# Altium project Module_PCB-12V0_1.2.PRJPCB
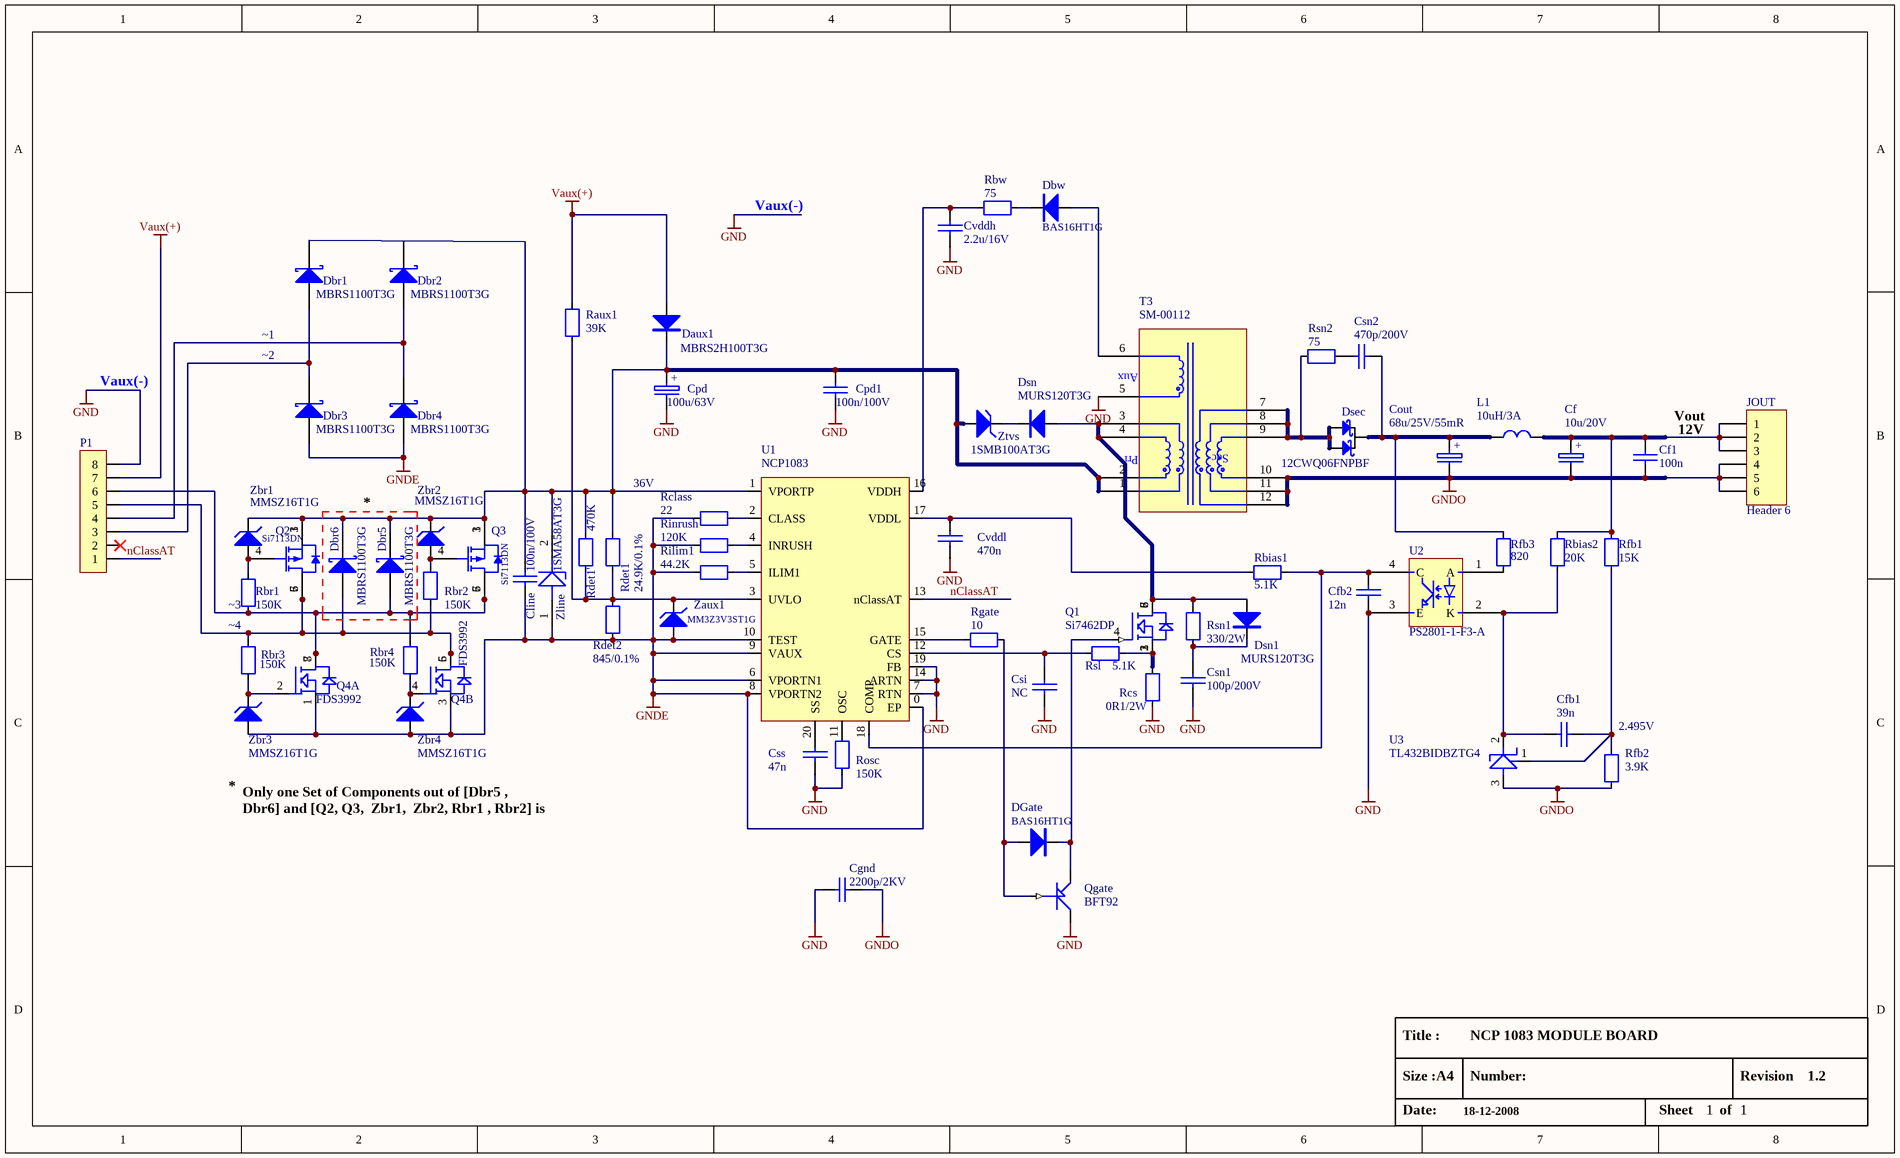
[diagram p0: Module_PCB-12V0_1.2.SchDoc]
1 sheet, 69 parts. Net scope: global (net labels, ports and power ports of the same name join across sheets).
Board file: Module_PCB-12V0_1.2.PcbDoc

## Sheet Module_PCB-12V0_1.2.SchDoc: NCP1081_COMPACT_MODULE
size Legal; Revision: 1; SheetNumber: 1; SheetTotal: 1; PageSetup: Record=PageOptions|CenterHorizontal=True|CenterVertical=True|PrintScale=0.80|XCorrection=1.00|YCorrection=1.00|PrintKind=2|BorderSize=5000000|LeftOffset=0|BottomOffset=0|Orientation=2|PaperLength=1000|PaperWidth=1000|Scale=100|PaperSource=7|PrintQuality=-4|MediaType=1|DitherType=10|PaperKind=A4|PrintScaleMode=1

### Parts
Cf  10u/20V  [C-TANT-B]
Cf1  100n  [0805-C-S]
Cfb1  39n  [0805-C-S]
Cfb2  12n  [0805-C-S]
Cgnd  2200p/2KV  [1812]
Cline  100n/100V  [1206-C]
Cout  68u/25V/55mR  [C-TANT-E]
Cpd  100u/63V  [CRD10.0L17.0RM5.0]
Cpd1  100n/100V  [1206-C]
Csi  NC  [0805-C-S]
Csn1  100p/200V  [0805-C-S]
Csn2  470p/200V  [0805-C-S]
Css  47n  [0805-C-S]
Cvddh  2.2u/16V  [0805-C-S]
Cvddl  470n  [0805-C-S]
Daux1  MBRS2H100T3G  [403A-03]
Dbr1  MBRS1100T3G  [403A-03]
Dbr2  MBRS1100T3G  [403A-03]
Dbr3  MBRS1100T3G  [403A-03]
Dbr4  MBRS1100T3G  [403A-03]
Dbr5  MBRS1100T3G  [403A-03_D]
Dbr6  MBRS1100T3G  [403A-03_D]
Dbw  BAS16HT1G  [SOD323]
DGate  BAS16HT1G  [SOD323]
Dsec  12CWQ06FNPBF  [DPAK]
Dsn  MURS120T3G  [403A-03]
Dsn1  MURS120T3G  [403A-03]
JOUT  Header 6  [HDR1X6]
L1  10uH/3A  [10x12]
P1  Header 8  [HDR1X8]  (value not drawn)
Q1  Si7462DP  [SOPP8]
Q2  Si7113DN  [POWERPACK 1212-8]
Q3  Si7113DN  [POWERPACK 1212-8]
Q4  FDS3992  [SO-8]  (parts A,B of 2)
Qgate  BFT92  [SOT23]
Raux1  39K  [0805-R-S]
Rbias1  5.1K  [0805-R-S]
Rbias2  20K  [0805-R-S]
Rbr1  150K  [0805-R-S]
Rbr2  150K  [0805-R-S]
Rbr3  150K  [0805-R-S]
Rbr4  150K  [0805-R-S]
Rbw  75  [0805-R-S]
Rclass  22  [0805-R-S]
Rcs  0R1/2W  [2512-S]
Rdet1  24.9K/0.1%  [0805-R-S]
Rdet1'  470K  [0805-R-S]
Rdet2  845/0.1%  [0805-R-S]
Rfb1  15K  [0805-R-S]
Rfb2  3.9K  [0805-R-S]
Rfb3  820  [0805-R-S]
Rgate  10  [0805-R-S]
Rilim1  44.2K  [0805-R-S]
Rinrush  120K  [0805-R-S]
Rosc  150K  [0805-R-S]
Rsl  5.1K  [0805-R-S]
Rsn1  330/2W  [2512-S]
Rsn2  75  [0805-R-S]
T3  SM-00112  [NUFLUX]
U1  NCP1083  [TSSOPEP20]
U2  PS2801-1-F3-A  [SSOP4]
U3  TL432BIDBZTG4  [SOT23]
Zaux1  MM3Z3V3ST1G  [SOD323]
Zbr1  MMSZ16T1G  [SOD123]
Zbr2  MMSZ16T1G  [SOD123]
Zbr3  MMSZ16T1G  [SOD123]
Zbr4  MMSZ16T1G  [SOD123]
Zline  1SMA58AT3G  [SMA]
Ztvs  1SMB100AT3G  [403A-03]

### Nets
GND: Cfb2.2 Cgnd.1 Cpd.2 Cpd1.1 Csi.2 Csn1.2 Css.2 Cvddh.2 Cvddl.2 P1.8 Qgate.3(C) Rcs.1 Rosc.1 T3.5 U1.7(RTN) U1.14(ARTN) U1.19(FB) U2.3(E)
GNDE: Cline.1 Dbr3.1(A) Dbr4.1(A) Q4.1(S) Q4.3(S) Rclass.2 Rdet2.2 Rilim1.1 Rinrush.1 U1.0(EP) U1.6(VPORTN1) U1.8(VPORTN2) U1.9(VAUX) U1.10(TEST) Zaux1.1(A) Zbr3.1(A) Zbr4.1(A) Zline.1
GNDO: Cf.2 Cf1.2 Cgnd.2 Cout.2 JOUT.4 JOUT.5 JOUT.6 Rfb2.1 T3.10 T3.11 T3.12 U3.3(A)
Vaux(+): Daux1.1(A) P1.7 Raux1.1
nClassAT: P1.1 U1.13(nClassAT)
NetCf_1: Cf.1 Cf1.1 JOUT.1 JOUT.2 JOUT.3 L1.2 Rbias2.2 Rfb1.1
NetCfb1_1: Cfb1.1 Rfb1.2 Rfb2.2 U3.1(VREF)
NetCfb1_2: Cfb1.2 Rbias2.1 U2.2(K) U3.2(C)
NetCfb2_1: Cfb2.1 Rbias1.1 U1.18(COMP) U2.4(C)
NetCline_2: Cline.2 Cpd.1 Cpd1.2 Daux1.2(K) Dbr1.2(K) Dbr5.2(K) Dbr6.2(K) Q2.1(S) Q2.2(S) Q2.3(S) Q3.1(S) Q3.2(S) Q3.3(S) Rdet1.1 Rdet1'.1 T3.1 T3.2 U1.1(VPORTP) Zbr1.2(K) Zbr2.2(K) Zline.2 Ztvs.1(A)
NetCout_1: Cout.1 Csn2.1 Dsec.4(K) L1.1 Rfb3.1
NetCsi_1: Csi.1 Rsl.2 U1.12(CS)
NetCsn1_1: Csn1.1 Dsn1.2(K) Rsn1.1
NetCsn2_2: Csn2.2 Rsn2.1
NetCss_1: Css.1 U1.20(SS)
NetCvddh_1: Cvddh.1 Rbw.1 U1.16(VDDH)
NetCvddl_1: Cvddl.1 Rbias1.2 U1.17(VDDL)
NetDbr1_1: Dbr1.1(A) Dbr3.2(K) P1.3
NetDbr2_1: Dbr2.1(A) Dbr4.2(K) P1.4
NetDbr5_1: Dbr5.1(A) P1.6 Q3.5(D) Q3.6(D) Q3.7(D) Q3.8(D) Q4.7(D) Q4.8(D) Rbr1.2 Rbr4.1
NetDbr6_1: Dbr6.1(A) P1.5 Q2.5(D) Q2.6(D) Q2.7(D) Q2.8(D) Q4.5(D) Q4.6(D) Rbr2.2 Rbr3.1
NetDbw_1: Dbw.1(A) T3.6
NetDbw_2: Dbw.2(K) Rbw.2
NetDGate_1: DGate.1(A) Qgate.1(B) Rgate.1
NetDGate_2: DGate.2(K) Q1.4(G) Qgate.2(E)
NetDsec_1: Dsec.1(A) Dsec.3(A) Rsn2.2 T3.7 T3.8 T3.9
NetDsn_1: Dsn.1(A) Dsn1.1(A) Q1.5(D) Q1.6(D) Q1.7(D) Q1.8(D) Rsn1.2 T3.3 T3.4
NetDsn_2: Dsn.2(K) Ztvs.2(K)
NetQ1_1: Q1.1(S) Q1.2(S) Q1.3(S) Rcs.2 Rsl.1
NetQ2_4: Q2.4(G) Rbr1.1 Zbr1.1(A)
NetQ3_4: Q3.4(G) Rbr2.1 Zbr2.1(A)
NetQ4_2: Q4.2(S) Rbr3.2 Zbr3.2(K)
NetQ4_4: Q4.4(S) Rbr4.2 Zbr4.2(K)
NetRaux1_2: Raux1.2 Rdet1.2 Rdet1'.2 Rdet2.1 U1.3(UVLO) Zaux1.2(K)
NetRclass_1: Rclass.1 U1.2(CLASS)
NetRfb3_2: Rfb3.2 U2.1(A)
NetRgate_2: Rgate.2 U1.15(GATE)
NetRilim1_2: Rilim1.2 U1.5(ILIM1)
NetRinrush_2: Rinrush.2 U1.4(INRUSH)
NetRosc_2: Rosc.2 U1.11(OSC)

Not connected (* = marked no-connect by the designer): Dbr2 2(K); P1 2*

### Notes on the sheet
- Vaux(-)
- |
- Vout
- 12V
- *
- 36V
- (near Rbr1) ~3
- ~4
- (near Rfb2) 2.495V
- Only one Set of Components out of [Dbr5 , Dbr6] and [Q2, Q3,  Zbr1,  Zbr2, Rbr1 , Rbr2] is used
- Title :
- NCP 1083 MODULE BOARD
- Size :
- A4
- Number:
- Revision
- 1.2
- Date:
- 18-12-2008
- Sheet
- 1
- of

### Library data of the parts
Cf Cout = CAP POL: Capacitor Tant Polar; Manufacturer: AVX; Filter: C; Remark: TPME686K025R0055 - AVX - CAPACITOR, 68UF 25V E CASE; Currency: GBP
Cf1 Cfb1 = CAP: Capacitor; Manufacturer: Samsung; Filter: C; Remark: C0805 39nF 50V X7R SAMSUNG 39nF 50V X7R +-10%; Currency: EUR
Cfb2 = CAP: Capacitor; Manufacturer: Samsung; Filter: C; Remark: C0805 12nF 50V X7R SAMSUNG 12nF 50V X7R +-10%; Currency: EUR
Cgnd = CAP: Capacitor; Manufacturer: AVX; Filter: C; Remark: 1812GC222KAT1A - AVX - CAPACITOR, 2200PF 2000V 1812; Currency: GBP
Cline Cpd1 = CAP: Capacitor; Manufacturer: Samsung; Filter: C; Remark: C1206 100nF 100V X7R SAMSUNG 100nF 100V X7R +-10%; Currency: EUR
Cpd = CAP POL: Capacitor Elec Polar; Manufacturer: Hitano; Filter: C; Remark: 100uF 63V 100kHz EXR 10x16; Currency: EUR
Csi = CAP: Capacitor; Filter: C; Remark: Not Defined
Csn1 = CAP: Capacitor; Manufacturer: AVX; Filter: C; Remark: 08052A471JAT2A - AVX - CAPACITOR, 470PF 200V NP0 0805; Currency: GBP
Csn2 = CAP: Capacitor; Manufacturer: Samsung; Filter: C; Remark: C0805 470pF 50V X7R SAMSUNG 470pF 50V X7R +-10%; Currency: EUR
Css = CAP: Capacitor; Manufacturer: Samsung; Filter: C; Remark: C0805 47nF 50V X7R SAMSUNG 47nF 50V X7R +-10%  - 47n/6V; Currency: EUR
Cvddh = CAP: Capacitor; Manufacturer: Samsung; Filter: C; Remark: C0805 2.2uF 16V Y5V SAMSUNG 2.2uF 16V Y5V +80-20% - 1-2.2u/20V/0.1R; Currency: EUR
Cvddl = CAP: Capacitor; Manufacturer: Samsung; Filter: C; Remark: C0805 470nF 50V Y5V SAMSUNG 470nF 50V Y5V +80-20% - 330-470n/6V/0.1R; Currency: EUR
Daux1 = DIODE: Diode Schottky; Manufacturer: ON Semi; Remark: IF(AV)=1A; VRRM=200V; IFSM=40A; VF=0.875V; Filter: D; Currency: GBP
Dbr1-Dbr6 = Diode 10TQ035: Diode Schottky; Note: Terminal 2 is the TAB and is electrically connected to the cathode
Dbw DGate Dsn Dsn1 = DIODE: Manufacturer: ON Semi; Remark: IF(AV)=1A; VRRM=200V; IFSM=40A; VF=0.875V; Filter: D; Currency: GBP
Dsec = DUAL_DIODE: Diode Schottky; Manufacturer: VISHAY FORMERLY IRF; Remark: IF(AV)=12A; VRRM=100V; IFSM=330A; VF=0.65V; Filter: D; Currency: GBP
JOUT = Header 6: Header, 6-Pin
L1 = INDUCTOR02: Secondary Filter; Manufacturer: Wurth Elektronik; Filter: L; Remark: L=1.2uH; Rdc=0.015Ohm; Idc=3.1A; Isat=2.8A; SRF=150.0MHz
P1 = Header 8: Header, 8-Pin
Q1 = MOSFET N SOICN8 2: MOSFET N-CHANNEL; Manufacturer: VISHAY SILICONIX; Filter: Q; Remark: ID=5.3(40)A; VDS=200V; VGS=+/-20V; VGS(th)=(2.0-4.5)V; rDS(on)=(65-90)mOhm; Currency: GBP
Q2 Q3 = Si7113DN: MOSFET P-Channel
Q4 = MOSFET_N_SOIC8: MOSFET N-CHANNEL; Manufacturer: VISHAY SILICONIX; Filter: Q; Remark: ID=5.3(40)A; VDS=200V; VGS=+/-20V; VGS(th)=(2.0-4.5)V; rDS(on)=(65-90)mOhm; Currency: GBP
Qgate = PNP-BEC: Transistor PNP; Manufacturer: NXP; Filter: Q; Remark: Vcbo=-20V; Vceo=-15V; Ic=-25mA; Ptot=300mW; hFE=50;fT=5GHz; Currency: GBP
Raux1 Rclass = RESISTOR_1: Resistor; Manufacturer: Uni ohm; Filter: R; Remark: R0805 22R 1% RES SMD 0805 1% 200ppm 22R 1/8W; Currency: USD
Rbias1 = RESISTOR_1: Resistor; Filter: R; Remark: Not Defined
Rbias2 = RESISTOR_1: Resistor; Manufacturer: Uni ohm; Filter: R; Remark: R0805 20K 5% RES SMD 0805 5% 200ppm 20K 1/8W; Currency: USD
Rbr1-Rbr4 Rfb1 = RESISTOR_1: Resistor; Manufacturer: Uni ohm; Filter: R; Remark: R0805 15K 1% RES SMD 0805 1% 100ppm 15K 1/8W; Currency: USD
Rbw Rsn2 = RESISTOR_1: Resistor; Manufacturer: Uni ohm; Filter: R; Remark: R0805 75R 1% RES SMD 0805 1% 200ppm 75R 1/8W; Currency: USD
Rcs = RESISTOR_1: Resistor; Manufacturer: PHYCOMP; Filter: R; Remark: 232276430107 - PHYCOMP - RESISTOR, 2512 2W 0R1 1%; Currency: GBP
Rdet1 Rdet1' = RESISTOR_1: Resistor; Manufacturer: Uni ohm; Filter: R; Remark: R0805 24K 1% RES SMD 0805 1% 100ppm 24K 1/8W; Currency: USD
Rdet2 = RESISTOR_1: Resistor; Manufacturer: Uni ohm; Filter: R; Remark: R0805 820R 1% RES SMD 0805 1% 100ppm 820R 1/8W; Currency: USD
Rfb2 = RESISTOR_1: Resistor; Manufacturer: Uni ohm; Filter: R; Remark: R0805 2.2K 1% RES SMD 0805 1% 100ppm 2.2K 1/8W; Currency: USD
Rfb3 = RESISTOR_1: Resistor; Manufacturer: Uni ohm; Filter: R; Remark: R0805 2.0K 1% RES SMD 0805 1% 100ppm 2.0K 1/8W; Currency: USD
Rgate = RESISTOR_1: Resistor; Manufacturer: Uni ohm; Filter: R; Remark: R0805 18R 5% RES SMD 0805 5% 200ppm 18R 1/8W; Currency: USD
Rilim1 = RESISTOR_1: Resistor; Manufacturer: Uni ohm; Filter: R; Remark: R0805 51K 1% RES SMD 0805 1% 100ppm 51K 1/8W - 50k-95k/1%; Currency: USD
Rinrush = RESISTOR_1: Resistor; Manufacturer: Uni ohm; Filter: R; Remark: R0805 62K 1% RES SMD 0805 1% 100ppm 62K 1/8W - 57.6k-170k/1%; Currency: USD
Rosc = RESISTOR_1: Resistor; Manufacturer: WELWYN; Filter: R; Remark: PCF0805R 143KBI.T1 - WELWYN - RESISTOR, 0805 143K - >30k/1%; 143k/1%; Currency: GBP
Rsl = RESISTOR_1: Resistor; Manufacturer: Uni ohm; Filter: R; Remark: R0805 5.1K 5% RES SMD 0805 5% 200ppm 5.1K 1/8W; Currency: USD
Rsn1 = RESISTOR_1: Resistor; Manufacturer: VISHAY DALE; Filter: R; Remark: CRCW2512160RJNEG - VISHAY DALE - Thick Film Chip Resistor; Currency: GBP
T3 = COILCRAFT_POE300_50L: PoE Plus Transformer; Filter: T; Remark: 12 V, 2.5 A 30 W PoE Transformer
U1 = AMIS80101: Power over Ethernet controller; Manufacturer: ON Semi; Manufacturer Part Number: NCP1081_O2A; Remark: HIPO ASSP providing power management functions compliant with IEEE 802.3af; Filter: U
U2 = PS2801_1: HIGH ISOLATION VOLTAGE SSOP PHOTOCOUPLER; Manufacturer: CEL - NEC; Filter: U; Remark: BV=2500Vrms; VCEO=80V; tr=3us; tf=5us; IF=IC=50mA; CTR=(80-600)%; Currency: USD
U3 = TL431: Programmable Shunt Voltage Reference; Manufacturer: TI; Filter: U; Remark: Vref=2.495V; Iref=4uA; Ik-min=1mA; Uin=+2.5/36V; Currency: GBP
Zaux1 = DIODE_SCHOTTKY: Diode Zener 3.3V; Manufacturer: VISHAY FORMERLY IRF; Remark: IF(AV)=12A; VRRM=100V; IFSM=330A; VF=0.65V; Filter: D; Currency: GBP
Zbr1-Zbr4 = DIODE_SCHOTTKY: Diode Zener 16V; Manufacturer: VISHAY FORMERLY IRF; Remark: IF(AV)=12A; VRRM=100V; IFSM=330A; VF=0.65V; Filter: D; Currency: GBP
Zline = SMAJ58A: Diode TVS 58V; Manufacturer: Littelfuse Inc; Filter: D; Remark: Irm=1uA; Vrm=58V; Vbr=64.4V; Ir=1mA; VCL=(93.6-121)V; IPP=(4.3-19)A; Currency: USD
Ztvs = DIODE_SCHOTTKY: Diode TVS 100V; Manufacturer: VISHAY FORMERLY IRF; Remark: IF(AV)=12A; VRRM=100V; IFSM=330A; VF=0.65V; Filter: D; Currency: GBP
